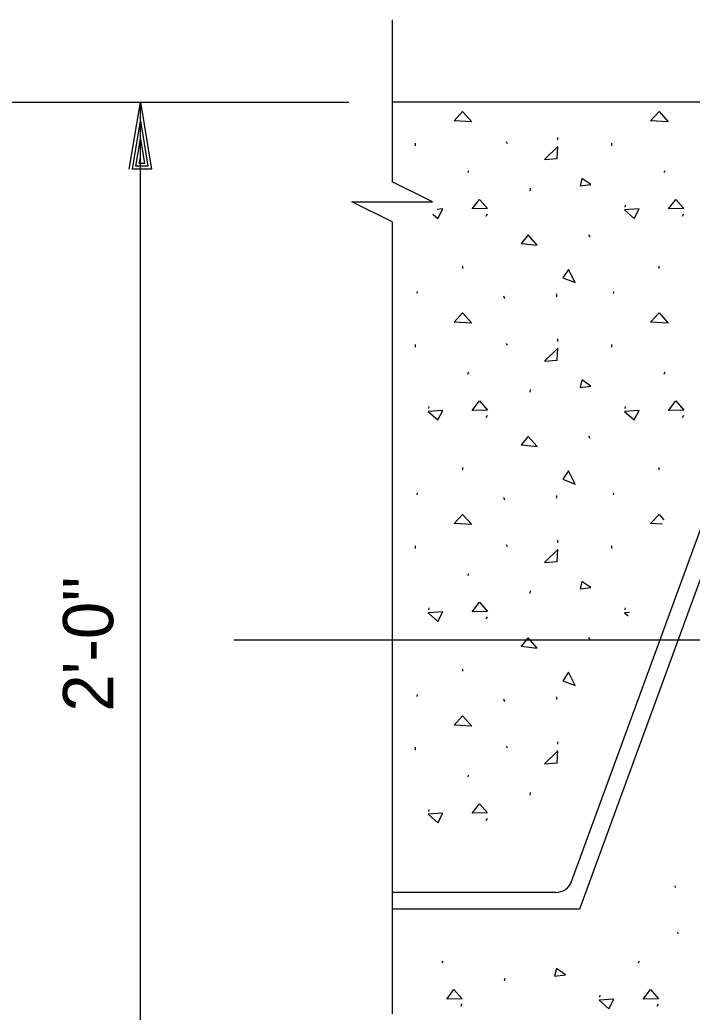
# Model space of a CAD drawing. Extents: x 22369.6 to 22384.3, y 22369.6 to 22381.8.
# Drawn here: x 22374.021 to 22374.645, y 22378.766 to 22379.688 of the extents above; entities that cross this region are included whole.
import ezdxf

# ---------------------------------------------------------------- set-up
doc = ezdxf.new("R2010")
doc.units = 0
for name, color, linetype in [('Level 1', 7, 'Continuous'), ('Level 10', 7, 'Continuous'), ('Level 4', 7, 'Continuous'), ('Level 8', 7, 'Continuous')]:
    doc.layers.add(name, color=color, linetype=linetype)

msp = doc.modelspace()

# ---------------------------------------------------------------- linework, layer by layer
at = {"layer": 'Level 1'}
for p, q in [((22374.36676, 22379.68776), (22374.36676, 22379.53748)), ((22373.69555, 22379.61141), (22374.32633, 22379.61141)), ((22374.13299, 22378.61191), (22374.13299, 22379.61141)), ((22374.13299, 22379.61141), (22374.13299, 22379.61141)), ((22374.13299, 22379.59408), (22374.13299, 22379.59408)), ((22374.36676, 22379.5001), (22374.36676, 22378.76496)), ((22374.36676, 22379.45534), (22374.36676, 22378.78598)), ((22374.38988, 22379.43365), (22374.39022, 22379.43553)), ((22374.38834, 22379.38386), (22374.38834, 22379.38636)), ((22374.53313, 22378.88777), (22374.70631, 22379.36141)), ((22374.71347, 22379.33556), (22374.54031, 22378.86191)), ((22374.96906, 22379.11166), (22374.21981, 22379.11166)), ((22374.51848, 22378.87752), (22374.36676, 22378.87752)), ((22374.54031, 22378.86191), (22374.36676, 22378.86191))]:
    msp.add_line(p, q, dxfattribs=at)
for points in [[(22374.12265, 22379.54908), (22374.13299, 22379.61141), (22374.14332, 22379.54908), (22374.12565, 22379.54908), (22374.13299, 22379.59408), (22374.13999, 22379.55175), (22374.12865, 22379.55175), (22374.13299, 22379.57741), (22374.13665, 22379.55441), (22374.13199, 22379.55441), (22374.13299, 22379.56008)], [(22374.36676, 22379.5001), (22374.32926, 22379.51873), (22374.40418, 22379.51873), (22374.36676, 22379.53748)]]:
    msp.add_lwpolyline(points, dxfattribs=at)
msp.add_arc((22374.51848, 22378.89313), 0.01561, 270, 339.92259, dxfattribs=at)
at = {"layer": 'Level 10'}
msp.add_line((22374.91698, 22379.61141), (22374.36676, 22379.61141), dxfattribs=at)
at = {"layer": 'Level 8'}
for p, q in [((22374.52043, 22379.57628), (22374.52043, 22379.57861)), ((22374.38834, 22379.5709), (22374.38834, 22379.5734)), ((22374.47355, 22379.57261), (22374.47284, 22379.5744)), ((22374.57055, 22379.5709), (22374.57055, 22379.5734)), ((22374.43672, 22379.5459), (22374.43763, 22379.54786)), ((22374.61893, 22379.5459), (22374.61984, 22379.54786)), ((22374.49455, 22379.52911), (22374.49493, 22379.53153)), ((22374.58293, 22379.5139), (22374.58309, 22379.51574)), ((22374.45393, 22379.50557), (22374.45518, 22379.50765)), ((22374.63613, 22379.50557), (22374.63738, 22379.50765)), ((22374.5503, 22379.48607), (22374.54918, 22379.48828)), ((22374.43226, 22379.45703), (22374.43209, 22379.45907)), ((22374.61447, 22379.45703), (22374.6143, 22379.45907)), ((22374.47105, 22379.4287), (22374.47034, 22379.4312)), ((22374.51955, 22379.4307), (22374.51955, 22379.4332)), ((22374.57209, 22379.43365), (22374.57243, 22379.43553)), ((22374.47355, 22379.38557), (22374.47284, 22379.38736)), ((22374.52043, 22379.38924), (22374.52043, 22379.39157)), ((22374.57055, 22379.38386), (22374.57055, 22379.38636)), ((22374.43672, 22379.35886), (22374.43763, 22379.36082)), ((22374.61893, 22379.35886), (22374.61984, 22379.36082)), ((22374.49455, 22379.34207), (22374.49493, 22379.34449)), ((22374.40072, 22379.32686), (22374.40088, 22379.3287)), ((22374.58293, 22379.32686), (22374.58309, 22379.3287)), ((22374.45393, 22379.31853), (22374.45518, 22379.32061)), ((22374.63613, 22379.31853), (22374.63738, 22379.32061)), ((22374.5503, 22379.29903), (22374.54918, 22379.30124)), ((22374.43226, 22379.26999), (22374.43209, 22379.27203)), ((22374.61447, 22379.26999), (22374.6143, 22379.27203)), ((22374.38988, 22379.24661), (22374.39022, 22379.24849)), ((22374.51955, 22379.24365), (22374.51955, 22379.24615)), ((22374.57209, 22379.24661), (22374.57243, 22379.24849)), ((22374.47105, 22379.24165), (22374.47034, 22379.24415)), ((22374.38834, 22379.19682), (22374.38834, 22379.19932)), ((22374.47355, 22379.19853), (22374.47284, 22379.20032)), ((22374.52043, 22379.2022), (22374.52043, 22379.20453)), ((22374.57055, 22379.19682), (22374.57055, 22379.19932)), ((22374.43672, 22379.17182), (22374.43763, 22379.17378)), ((22374.49455, 22379.15503), (22374.49493, 22379.15745)), ((22374.40072, 22379.13982), (22374.40088, 22379.14165)), ((22374.58293, 22379.13982), (22374.58309, 22379.14165)), ((22374.45393, 22379.13149), (22374.45518, 22379.13357)), ((22374.5503, 22379.11199), (22374.54918, 22379.1142)), ((22374.43226, 22379.08295), (22374.43209, 22379.08499)), ((22374.38988, 22379.05957), (22374.39022, 22379.06145)), ((22374.47105, 22379.05461), (22374.47034, 22379.05711)), ((22374.51955, 22379.05661), (22374.51955, 22379.05911)), ((22374.52043, 22379.01515), (22374.52043, 22379.01749)), ((22374.38834, 22379.00978), (22374.38834, 22379.01228)), ((22374.47355, 22379.01149), (22374.47284, 22379.01328)), ((22374.43672, 22378.98478), (22374.43763, 22378.98674)), ((22374.49455, 22378.96799), (22374.49493, 22378.9704)), ((22374.40072, 22378.95278), (22374.40088, 22378.95461)), ((22374.45393, 22378.94445), (22374.45518, 22378.94653)), ((22374.63218, 22378.83893), (22374.63147, 22378.84072)), ((22374.59534, 22378.81222), (22374.59626, 22378.81418)), ((22374.47097, 22378.79543), (22374.47134, 22378.79784)), ((22374.55934, 22378.78022), (22374.55951, 22378.78205)), ((22374.43034, 22378.77188), (22374.43159, 22378.77397)), ((22374.61255, 22378.77188), (22374.6138, 22378.77397))]:
    msp.add_line(p, q, dxfattribs=at)
for points in [[(22374.42409, 22379.59403), (22374.43201, 22379.60261), (22374.44051, 22379.59311)], [(22374.6063, 22379.59403), (22374.61422, 22379.60261), (22374.62272, 22379.59311)], [(22374.5198, 22379.5589), (22374.52043, 22379.57003), (22374.50809, 22379.55799)], [(22374.54093, 22379.53349), (22374.55105, 22379.53478), (22374.54255, 22379.54049)], [(22374.44084, 22379.51215), (22374.44755, 22379.52103), (22374.45509, 22379.51249)], [(22374.5823, 22379.5112), (22374.59118, 22379.50328), (22374.59593, 22379.51215)], [(22374.62305, 22379.51215), (22374.62976, 22379.52103), (22374.6373, 22379.51249)], [(22374.50118, 22379.47857), (22374.49293, 22379.48807), (22374.4863, 22379.4802)], [(22374.52497, 22379.4482), (22374.53634, 22379.44378), (22374.53034, 22379.45607)], [(22374.42409, 22379.40699), (22374.43201, 22379.41557), (22374.44051, 22379.40607)], [(22374.6063, 22379.40699), (22374.61422, 22379.41557), (22374.62272, 22379.40607)], [(22374.5198, 22379.37186), (22374.52043, 22379.38299), (22374.50809, 22379.37095)], [(22374.54093, 22379.34645), (22374.55105, 22379.34774), (22374.54255, 22379.35345)], [(22374.44084, 22379.32511), (22374.44755, 22379.33399), (22374.45509, 22379.32545)], [(22374.62305, 22379.32511), (22374.62976, 22379.33399), (22374.6373, 22379.32545)], [(22374.40009, 22379.32415), (22374.40897, 22379.31624), (22374.41372, 22379.32511)], [(22374.5823, 22379.32415), (22374.59118, 22379.31624), (22374.59593, 22379.32511)], [(22374.50118, 22379.29153), (22374.49293, 22379.30103), (22374.4863, 22379.29315)], [(22374.52497, 22379.26115), (22374.53634, 22379.25674), (22374.53034, 22379.26903)], [(22374.42409, 22379.21995), (22374.43201, 22379.22853), (22374.44051, 22379.21903)], [(22374.5198, 22379.18482), (22374.52043, 22379.19595), (22374.50809, 22379.1839)], [(22374.54093, 22379.1594), (22374.55105, 22379.1607), (22374.54255, 22379.1664)], [(22374.44084, 22379.13807), (22374.44755, 22379.14695), (22374.45509, 22379.1384)], [(22374.40009, 22379.13711), (22374.40897, 22379.1292), (22374.41372, 22379.13807)], [(22374.50118, 22379.10449), (22374.49293, 22379.11399), (22374.4863, 22379.10611)], [(22374.52497, 22379.07411), (22374.53634, 22379.0697), (22374.53034, 22379.08199)], [(22374.42409, 22379.0329), (22374.43201, 22379.04149), (22374.44051, 22379.03199)], [(22374.44084, 22378.95103), (22374.44755, 22378.9599), (22374.45509, 22378.95136)], [(22374.40009, 22378.95007), (22374.40897, 22378.94215), (22374.41372, 22378.95103)], [(22374.51734, 22378.7998), (22374.52747, 22378.80109), (22374.51897, 22378.8068)], [(22374.41726, 22378.77847), (22374.42397, 22378.78734), (22374.43151, 22378.7788)], [(22374.59947, 22378.77847), (22374.60618, 22378.78734), (22374.61372, 22378.7788)], [(22374.55872, 22378.77751), (22374.56759, 22378.76959), (22374.57234, 22378.77847)]]:
    msp.add_lwpolyline(points, close=True, dxfattribs=at)
for points in [[(22374.41372, 22379.51215), (22374.40834, 22379.51177)], [(22374.40897, 22379.50328), (22374.41372, 22379.51215)], [(22374.40445, 22379.50731), (22374.40897, 22379.50328)], [(22374.6063, 22379.21995), (22374.61422, 22379.22853)], [(22374.61422, 22379.22853), (22374.61869, 22379.22354)], [(22374.61713, 22379.21934), (22374.6063, 22379.21995)], [(22374.58671, 22379.13743), (22374.5823, 22379.13711)], [(22374.5823, 22379.13711), (22374.58552, 22379.13425)], [(22374.52043, 22379.0089), (22374.50809, 22378.99686)], [(22374.5198, 22378.99778), (22374.52043, 22379.0089)], [(22374.50809, 22378.99686), (22374.5198, 22378.99778)], [(22374.62968, 22378.88205), (22374.6292, 22378.88374)], [(22374.41313, 22378.81222), (22374.414, 22378.81407)]]:
    msp.add_lwpolyline(points, dxfattribs=at)

# ---------------------------------------------------------------- texts
at = {"layer": 'Level 4'}
msp.add_text("2'-0''", height=0.046625, rotation=90, dxfattribs=at).set_placement((22374.10774, 22379.04539))

doc.saveas('drawing.dxf')
